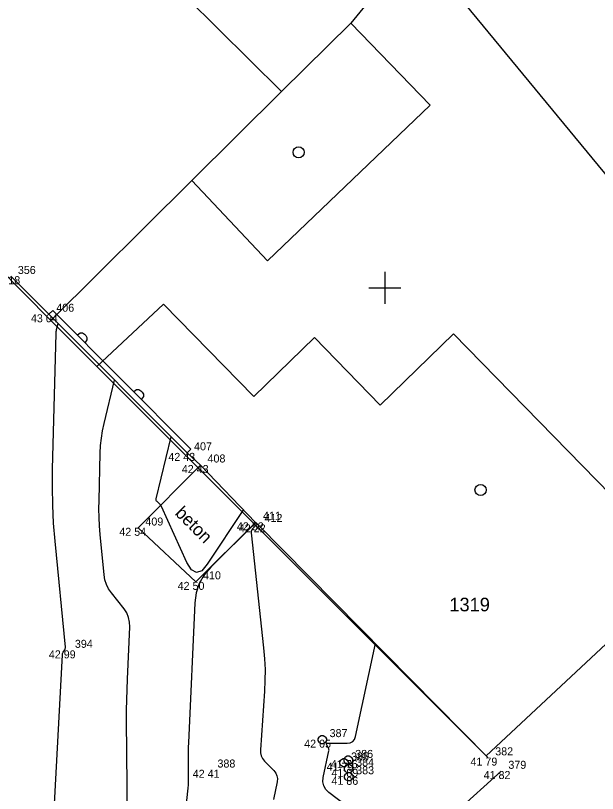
# Model space of a CAD drawing. Extents: x -702257 to -701487, y -1009871 to -1008841.
# Drawn here: x -701711.52 to -701693.36, y -1009065.8 to -1009041.5 of the extents above; entities that cross this region are included whole.
import ezdxf

# ---------------------------------------------------------------- set-up
doc = ezdxf.new("R2010")
doc.units = 0
for name, color, linetype in [('Ex_Major Contours', 7, 'Continuous'), ('Ex_Minor Contours', 7, 'Continuous'), ('Z_betonova_konstrukce', 7, 'Continuous'), ('Z_body', 7, 'Continuous'), ('Z_body_cisla', 7, 'Continuous'), ('Z_body_vysky_redukovane', 7, 'Continuous'), ('Z_budova', 7, 'Continuous'), ('Z_cesta', 7, 'Continuous'), ('Z_hektometricka_sit', 7, 'Continuous'), ('Z_katastr_cisla_stavebni', 7, 'Continuous'), ('Z_katastr_hranice', 7, 'Continuous'), ('Z_katastr_vnitrni_kresba', 7, 'Continuous'), ('Z_katastr_znacky_budov', 7, 'Continuous'), ('Z_ploty', 7, 'Continuous'), ('Z_ploty_znacky', 7, 'Continuous'), ('Z_popisy', 7, 'Continuous'), ('Z_site_vodovod_znaky', 7, 'Continuous'), ('Z_vstupy', 7, 'Continuous')]:
    doc.layers.add(name, color=color, linetype=linetype)

# ---------------------------------------------------------------- blocks, each defined once
blk = doc.blocks.new('POINT_DISPLAY')
blk.add_line((0, 0), (0, 0))
blk = doc.blocks.new('Z614')
for p, q in [((-0.13, 0.03), (-0.1, 0.08)), ((-0.13, -0.03), (-0.13, 0.03)), ((-0.1, 0.08), (-0.08, 0.1)), ((-0.08, 0.1), (-0.03, 0.13)), ((-0.03, 0.13), (0.03, 0.13)), ((0.03, 0.13), (0.08, 0.1)), ((0.08, 0.1), (0.1, 0.08)), ((0.1, 0.08), (0.13, 0.03)), ((0.13, 0.03), (0.13, -0.03)), ((-0.1, -0.08), (-0.13, -0.03)), ((-0.08, -0.1), (-0.1, -0.08)), ((-0.03, -0.13), (-0.08, -0.1)), ((0.03, -0.13), (-0.03, -0.13)), ((0.08, -0.1), (0.03, -0.13)), ((0.1, -0.08), (0.08, -0.1)), ((0.13, -0.03), (0.1, -0.08))]:
    blk.add_line(p, q)
blk = doc.blocks.new('Z216')
for p, q in [((-0.17, 0), (-0.15, 0.1)), ((-0.15, 0.1), (-0.1, 0.15)), ((-0.1, 0.15), (-0.03, 0.17)), ((-0.03, 0.17), (0.03, 0.17)), ((0.03, 0.17), (0.1, 0.15)), ((0.1, 0.15), (0.15, 0.1)), ((0.15, 0.1), (0.17, 0))]:
    blk.add_line(p, q)

msp = doc.modelspace()

# ---------------------------------------------------------------- linework, layer by layer
at = {"layer": 'Ex_Major Contours'}
for points in [[(-701710.334, -1009066.707), (-701710.061, -1009061.472), (-701710.059, -1009061.449), (-701710.053, -1009061.428), (-701710.045, -1009061.407), (-701710.035, -1009061.388), (-701709.987, -1009061.311), (-701709.977, -1009061.291), (-701709.97, -1009061.271), (-701709.967, -1009061.249), (-701709.967, -1009061.227), (-701710.288, -1009057.914), (-701710.334, -1009057.354), (-701710.362, -1009056.794), (-701710.374, -1009056.232), (-701710.368, -1009055.671), (-701710.259, -1009051.428), (-701710.258, -1009051.396), (-701710.254, -1009051.364), (-701710.249, -1009051.333), (-701710.243, -1009051.301), (-701710.197, -1009051.114)], [(-701701.177, -1009066.199), (-701701.74, -1009065.775), (-701701.841, -1009065.678), (-701701.904, -1009065.567), (-701701.929, -1009065.442), (-701701.917, -1009065.303), (-701701.741, -1009064.471), (-701701.738, -1009064.449), (-701701.739, -1009064.426), (-701701.745, -1009064.405), (-701701.753, -1009064.384), (-701701.816, -1009064.265), (-701701.817, -1009064.262), (-701701.818, -1009064.258), (-701701.818, -1009064.255), (-701701.817, -1009064.251), (-701701.813, -1009064.237), (-701701.811, -1009064.234), (-701701.809, -1009064.232), (-701701.806, -1009064.231), (-701701.803, -1009064.23), (-701701.169, -1009064.228), (-701701.073, -1009064.215), (-701700.998, -1009064.176), (-701700.944, -1009064.11), (-701700.911, -1009064.019), (-701700.291, -1009061.12)]]:
    msp.add_lwpolyline(points, dxfattribs=at)
at = {"layer": 'Ex_Minor Contours'}
for points in [[(-701708.031, -1009066.57), (-701708.054, -1009063.522), (-701708.054, -1009063.198), (-701708.05, -1009062.874), (-701708.042, -1009062.55), (-701708.029, -1009062.226), (-701707.955, -1009060.598), (-701707.961, -1009060.444), (-701707.994, -1009060.299), (-701708.052, -1009060.162), (-701708.137, -1009060.033), (-701708.53, -1009059.536), (-701708.618, -1009059.407), (-701708.685, -1009059.271), (-701708.732, -1009059.125), (-701708.757, -1009058.972), (-701708.88, -1009057.705), (-701708.901, -1009057.442), (-701708.915, -1009057.178), (-701708.92, -1009056.913), (-701708.917, -1009056.648), (-701708.879, -1009055.164), (-701708.867, -1009054.932), (-701708.843, -1009054.702), (-701708.807, -1009054.473), (-701708.758, -1009054.246), (-701708.431, -1009052.889)], [(-701704.412, -1009056.932), (-701705.537, -1009058.639), (-701705.713, -1009058.843), (-701705.877, -1009058.902), (-701706.031, -1009058.818), (-701706.173, -1009058.589), (-701706.97, -1009056.834), (-701706.981, -1009056.811), (-701706.995, -1009056.79), (-701707.011, -1009056.771), (-701707.029, -1009056.753), (-701707.105, -1009056.684), (-701707.121, -1009056.665), (-701707.131, -1009056.645), (-701707.134, -1009056.623), (-701707.132, -1009056.599), (-701706.665, -1009054.663)], [(-701704.026, -1009057.334), (-701705.432, -1009058.726), (-701705.638, -1009058.97), (-701705.79, -1009059.239), (-701705.888, -1009059.532), (-701705.93, -1009059.849), (-701706.129, -1009064.219), (-701706.134, -1009064.35), (-701706.137, -1009064.481), (-701706.139, -1009064.613), (-701706.139, -1009064.744), (-701706.134, -1009065.335), (-701706.135, -1009065.433), (-701706.139, -1009065.532), (-701706.145, -1009065.63), (-701706.155, -1009065.728), (-701706.199, -1009066.12)], [(-701703.976, -1009057.384), (-701704.127, -1009057.533), (-701704.148, -1009057.559), (-701704.162, -1009057.588), (-701704.169, -1009057.619), (-701704.169, -1009057.653), (-701703.779, -1009061.253), (-701703.75, -1009061.591), (-701703.736, -1009061.929), (-701703.737, -1009062.268), (-701703.753, -1009062.607), (-701703.88, -1009064.436), (-701703.877, -1009064.536), (-701703.855, -1009064.628), (-701703.812, -1009064.712), (-701703.75, -1009064.79), (-701703.461, -1009065.085), (-701703.401, -1009065.162), (-701703.363, -1009065.246), (-701703.35, -1009065.337), (-701703.359, -1009065.435), (-701703.476, -1009065.986)]]:
    msp.add_lwpolyline(points, dxfattribs=at)
at = {"layer": 'Z_betonova_konstrukce'}
for p, q in [((-701707.7, -1009057.5), (-701705.75, -1009055.54)), ((-701705.9, -1009059.19), (-701704.03, -1009057.33)), ((-701707.7, -1009057.5), (-701705.9, -1009059.19))]:
    msp.add_line(p, q, dxfattribs=at)
at = {"layer": 'Z_budova'}
for p, q in [((-701711.67, -1009049.64), (-701710.48, -1009050.83)), ((-701710.48, -1009050.83), (-701710.36, -1009050.71)), ((-701706.17, -1009055.16), (-701706.05, -1009055.04)), ((-701706.17, -1009055.16), (-701705.75, -1009055.54)), ((-701704.03, -1009057.33), (-701703.97, -1009057.39)), ((-701703.97, -1009057.39), (-701696.78, -1009064.68))]:
    msp.add_line(p, q, dxfattribs=at)
at = {"layer": 'Z_cesta'}
msp.add_line((-701696.37, -1009065.1), (-701699.02, -1009067.51), dxfattribs=at)
at = {"layer": 'Z_hektometricka_sit'}
for p, q in [((-701700, -1009049.5), (-701700, -1009050.5)), ((-701700, -1009049.5), (-701700, -1009050.5)), ((-701700.5, -1009050), (-701699.5, -1009050)), ((-701700.5, -1009050), (-701699.5, -1009050))]:
    msp.add_line(p, q, dxfattribs=at)
at = {"layer": 'Z_katastr_hranice'}
for p, q in [((-701699.04, -1009039.25), (-701701.06, -1009041.73)), ((-701686.39, -1009054.6), (-701699.04, -1009039.25)), ((-701710.42, -1009051.02), (-701721.41, -1009039.92)), ((-701701.06, -1009041.73), (-701703.22, -1009043.87)), ((-701703.22, -1009043.87), (-701706.02, -1009046.65)), ((-701706.02, -1009046.65), (-701710.42, -1009051.02)), ((-701708.98, -1009052.46), (-701710.42, -1009051.02)), ((-701696.83, -1009064.63), (-701708.98, -1009052.46)), ((-701687.98, -1009056.34), (-701696.83, -1009064.63))]:
    msp.add_line(p, q, dxfattribs=at)
at = {"layer": 'Z_katastr_vnitrni_kresba'}
for p, q in [((-701710.53, -1009036.63), (-701703.22, -1009043.87)), ((-701701.06, -1009041.73), (-701698.58, -1009044.3)), ((-701698.58, -1009044.3), (-701703.66, -1009049.16)), ((-701703.66, -1009049.16), (-701706.02, -1009046.65)), ((-701706.9, -1009050.51), (-701708.98, -1009052.46)), ((-701704.08, -1009053.4), (-701706.9, -1009050.51)), ((-701697.85, -1009051.44), (-701700.14, -1009053.67)), ((-701692.94, -1009056.47), (-701697.85, -1009051.44)), ((-701702.19, -1009051.56), (-701704.08, -1009053.4)), ((-701700.14, -1009053.67), (-701702.19, -1009051.56))]:
    msp.add_line(p, q, dxfattribs=at)
at = {"layer": 'Z_katastr_znacky_budov'}
for centre in [(-701702.687, -1009045.769), (-701697.007, -1009056.319)]:
    msp.add_circle(centre, 0.175, dxfattribs=at)
at = {"layer": 'Z_ploty'}
for p, q in [((-701710.36, -1009050.71), (-701706.05, -1009055.04)), ((-701710.48, -1009050.83), (-701706.17, -1009055.16))]:
    msp.add_line(p, q, dxfattribs=at)
at = {"layer": 'Z_vstupy'}
msp.add_line((-701705.75, -1009055.54), (-701704.03, -1009057.33), dxfattribs=at)

# ---------------------------------------------------------------- block references
at = {"layer": 'Z_body'}
for p in [(-701710.48, -1009050.83), (-701706.17, -1009055.16), (-701705.75, -1009055.54), (-701704.03, -1009057.33), (-701707.7, -1009057.5), (-701703.97, -1009057.39), (-701705.9, -1009059.19), (-701709.9, -1009061.33), (-701701.95, -1009064.12), (-701701.27, -1009064.84), (-701701.14, -1009064.76), (-701696.78, -1009064.68), (-701705.45, -1009065.06), (-701701.12, -1009065.03), (-701696.37, -1009065.1), (-701701.12, -1009065.28)]:
    msp.add_blockref('POINT_DISPLAY', p, dxfattribs=at)
at = {"layer": 'Z_ploty_znacky', "rotation": -45.10000000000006}
for p in [(-701709.47, -1009051.59), (-701707.71, -1009053.36)]:
    msp.add_blockref('Z216', p, dxfattribs=at)
at = {"layer": 'Z_site_vodovod_znaky'}
for p in [(-701701.95, -1009064.12), (-701701.14, -1009064.76), (-701701.27, -1009064.84), (-701701.12, -1009065.03), (-701701.12, -1009065.28)]:
    msp.add_blockref('Z614', p, dxfattribs=at)

# ---------------------------------------------------------------- texts
at = {"layer": 'Z_body_cisla'}
for s, p in [('356', (-701711.45, -1009049.57)), ('406', (-701710.25, -1009050.75)), ('407', (-701705.95, -1009055.08)), ('408', (-701705.53, -1009055.46)), ('411', (-701703.8, -1009057.25)), ('412', (-701703.75, -1009057.32)), ('409', (-701707.47, -1009057.43)), ('410', (-701705.67, -1009059.11)), ('394', (-701709.67, -1009061.25)), ('387', (-701701.72, -1009064.04)), ('382', (-701696.55, -1009064.61)), ('385', (-701701.05, -1009064.77)), ('386', (-701700.92, -1009064.69)), ('388', (-701705.22, -1009064.99)), ('384', (-701700.89, -1009064.95)), ('379', (-701696.14, -1009065.03)), ('383', (-701700.89, -1009065.2))]:
    msp.add_text(s, height=0.25, dxfattribs=at).set_placement(p)
at = {"layer": 'Z_body_vysky_redukovane'}
for s, p in [('43 18', (-701712.212, -1009049.89)), ('43 04', (-701711.042, -1009051.08)), ('42 43', (-701706.753, -1009055.41)), ('42 43', (-701706.333, -1009055.79)), ('42 52', (-701704.613, -1009057.58)), ('42 54', (-701708.283, -1009057.75)), ('42 22', (-701704.553, -1009057.64)), ('42 50', (-701706.463, -1009059.44)), ('42 99', (-701710.483, -1009061.58)), ('42 05', (-701702.513, -1009064.37)), ('41 79', (-701701.812, -1009065.09)), ('41 76', (-701701.682, -1009065.01)), ('41 79', (-701697.322, -1009064.93)), ('42 41', (-701705.992, -1009065.31)), ('41 89', (-701701.662, -1009065.28)), ('41 82', (-701696.912, -1009065.35)), ('41 86', (-701701.662, -1009065.53))]:
    msp.add_text(s, height=0.25, dxfattribs=at).set_placement(p)
at = {"layer": 'Z_katastr_cisla_stavebni'}
msp.add_text('1319', height=0.425, dxfattribs=at).set_placement((-701697.981, -1009060.11))
at = {"layer": 'Z_popisy'}
msp.add_text('beton', height=0.4, rotation=315, dxfattribs=at).set_placement((-701706.57, -1009057.07))

doc.saveas('drawing.dxf')
